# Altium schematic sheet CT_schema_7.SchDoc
size 278 x 170 mm
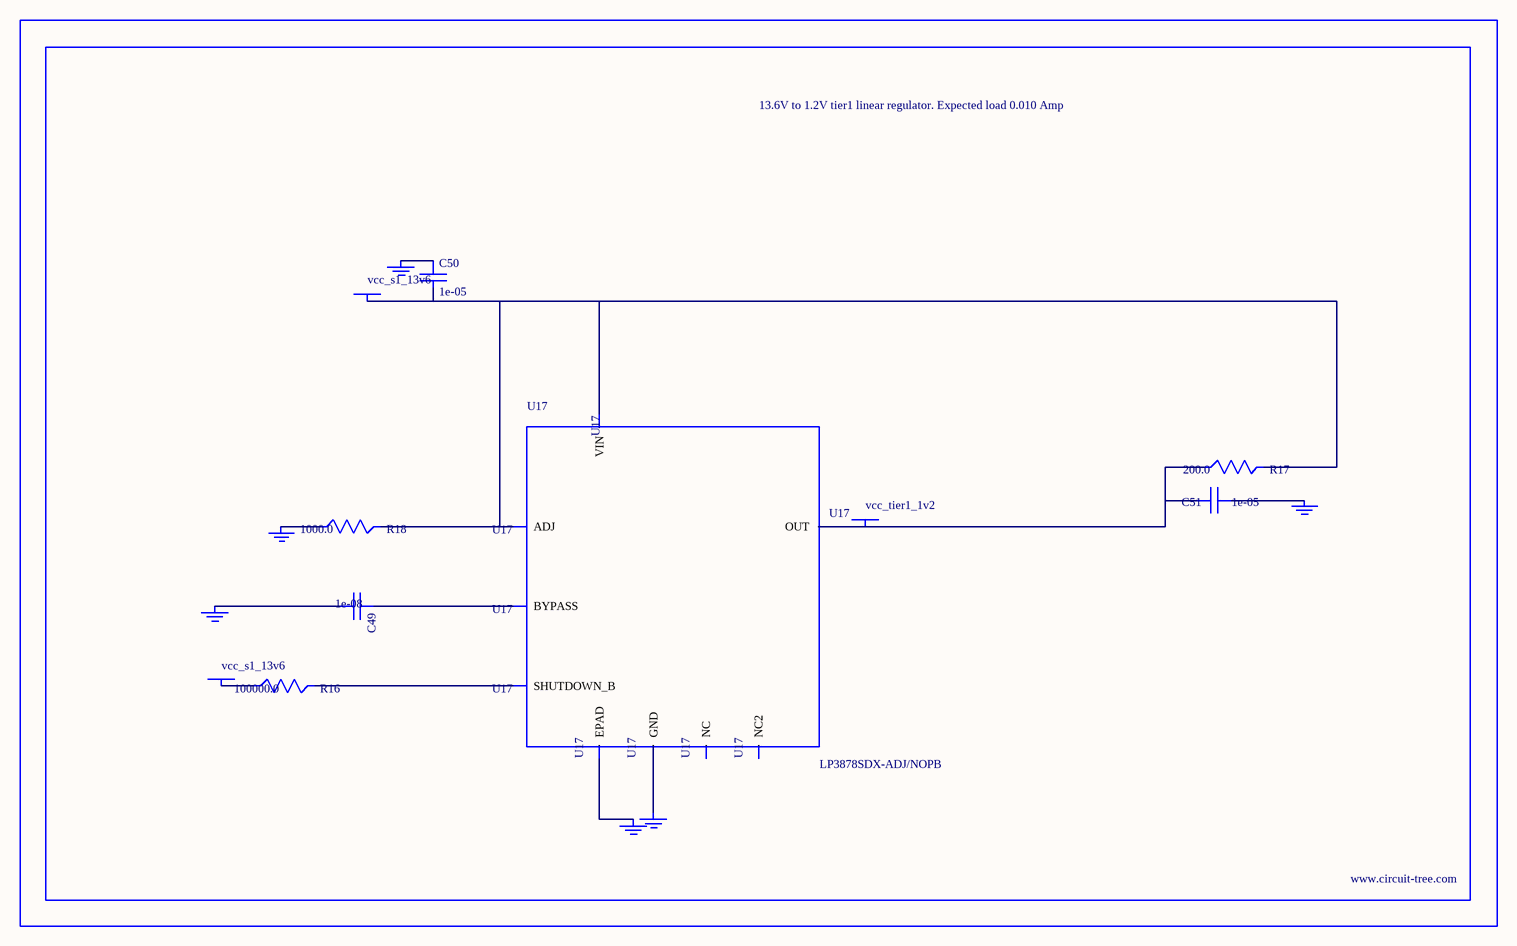
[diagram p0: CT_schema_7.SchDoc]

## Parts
BORDER6  (no value)
C49  1e-08  [C0402]
C50  1e-05  [C1210]
C51  1e-05  [C0805]
GND_INSTANCE_6_0  (no value)
GND_INSTANCE_6_1  (no value)
GND_INSTANCE_6_2  (no value)
GND_INSTANCE_6_3  (no value)
GND_INSTANCE_6_4  (no value)
GND_INSTANCE_6_5  (no value)
POWER_INSTANCE_6_0  vcc_s1_13v6
POWER_INSTANCE_6_1  vcc_s1_13v6
POWER_INSTANCE_6_2  vcc_tier1_1v2
R16  100000.0  [R0603]
R17  200.0  [R0603]
R18  1000.0  [R0603]
U17  LP3878SDX-ADJ/NOPB  [WSON-8]

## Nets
NetC49_1: C49.1 U17.1(BYPASS)
NetC49_2: C49.2 GND_INSTANCE_6_0.0(GND)
NetC50_1: C50.1 GND_INSTANCE_6_1.0(GND)
NetC50_2: C50.2 POWER_INSTANCE_6_0.0(PWR) R17.2 R18.2 U17.4(VIN) U17.6(ADJ)
NetC51_1: C51.1 GND_INSTANCE_6_2.0(GND)
NetC51_2: C51.2 POWER_INSTANCE_6_2.0(PWR) R17.1 U17.5(OUT)
NetGND_INSTANCE_6_3_0: GND_INSTANCE_6_3.0(GND) R18.1
NetGND_INSTANCE_6_4_0: GND_INSTANCE_6_4.0(GND) U17.PAD(EPAD)
NetGND_INSTANCE_6_5_0: GND_INSTANCE_6_5.0(GND) U17.3(GND)
NetPOWER_INSTANCE_6_1_0: POWER_INSTANCE_6_1.0(PWR) R16.1
NetR16_2: R16.2 U17.8(SHUTDOWN_B)

Not connected (* = marked no-connect by the designer): U17 2(NC) 7(NC2)

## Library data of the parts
BORDER6 = BORDER_PAGE6
C49 = C0402C103K3RAC
C50 = C1210C106K5PACTU
C51 = GRM219R60J106ME19D
GND_INSTANCE_6_0-GND_INSTANCE_6_5 = GND
POWER_INSTANCE_6_0-POWER_INSTANCE_6_2 = PWR
R16 = RC0603JR-07100KL
R17 = RC0603JR-07200RL
R18 = RC0603JR-071KL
